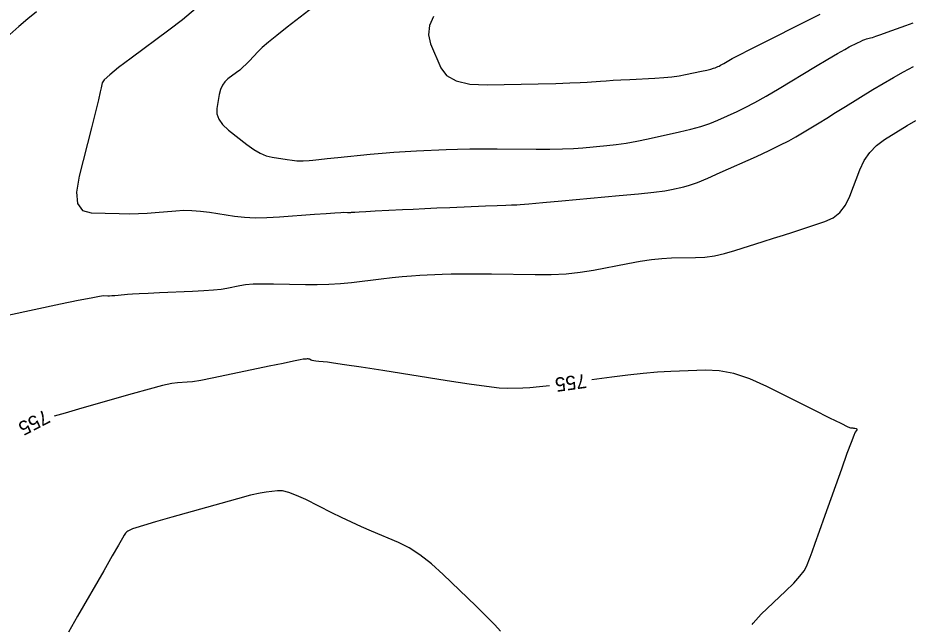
# Model space of a CAD drawing. Extents: x 2079879 to 2092887, y 778083 to 784051.
# Drawn here: x 2084668.2 to 2084844.9, y 781026.5 to 781146.9 of the extents above; entities that cross this region are included whole.
import ezdxf

# ---------------------------------------------------------------- set-up
doc = ezdxf.new("R2010")
doc.units = 0
doc.layers.add('DT_X_Contour_Major', color=7, linetype='Continuous')
doc.layers.add('DT_X_Contour_Minor', color=7, linetype='Continuous')

msp = doc.modelspace()

# ---------------------------------------------------------------- linework, layer by layer
at = {"layer": 'DT_X_Contour_Major'}
for points in [[(2084773.48, 781074.05), (2084771.5, 781073.82), (2084769.55, 781073.64), (2084768.14, 781073.57), (2084765.09, 781073.52), (2084763.49, 781073.59), (2084760.98, 781073.87), (2084757.55, 781074.34), (2084753.21, 781075), (2084740.41, 781077.03), (2084736.12, 781077.71), (2084732.88, 781078.21), (2084730.68, 781078.53), (2084729.51, 781078.69), (2084727.78, 781078.86), (2084727.2, 781078.92), (2084726.76, 781078.99), (2084726.44, 781079.05), (2084726.26, 781079.11), (2084725.94, 781079.27), (2084725.81, 781079.31), (2084725.66, 781079.34), (2084725.47, 781079.35), (2084725.26, 781079.33), (2084724.67, 781079.27), (2084724.08, 781079.16), (2084722.75, 781078.9), (2084720.7, 781078.47), (2084717.91, 781077.89), (2084709.51, 781076.12), (2084706.66, 781075.53), (2084704.41, 781075.1), (2084702.76, 781074.83), (2084701.72, 781074.72), (2084699.75, 781074.64), (2084698.63, 781074.48), (2084696.77, 781074.06), (2084694.15, 781073.37), (2084690.79, 781072.43), (2084680.82, 781069.57), (2084677.52, 781068.62), (2084675.32, 781068)], [(2084813.59, 781026.76), (2084813.79, 781027.06), (2084815.4, 781028.79), (2084820.22, 781033.4), (2084821.83, 781034.99), (2084823.06, 781036.33), (2084823.91, 781037.41), (2084824.36, 781038.24), (2084825.07, 781040.09), (2084825.45, 781041.13), (2084826.08, 781042.86), (2084826.95, 781045.28), (2084828.06, 781048.39), (2084831.34, 781057.62), (2084832.43, 781060.66), (2084833.24, 781062.87), (2084833.77, 781064.26), (2084834.01, 781064.81), (2084834.29, 781065.18), (2084834.37, 781065.31), (2084834.39, 781065.4), (2084834.35, 781065.47), (2084834.26, 781065.5), (2084833.95, 781065.56), (2084833.84, 781065.58), (2084833.72, 781065.59), (2084833.6, 781065.61), (2084833.47, 781065.62), (2084833.14, 781065.65), (2084832.6, 781065.87), (2084831.2, 781066.54), (2084828.96, 781067.64), (2084825.87, 781069.18), (2084816.51, 781073.86), (2084813.12, 781075.38), (2084809.96, 781076.43), (2084807.04, 781077.02), (2084804.36, 781077.15), (2084797.51, 781076.86), (2084794.85, 781076.7), (2084792.01, 781076.47), (2084788.99, 781076.14), (2084785.79, 781075.73), (2084781.8, 781075.18)]]:
    msp.add_lwpolyline(points, dxfattribs=at)
at = {"layer": 'DT_X_Contour_Minor'}
for points in [[(2084703.34, 781148.68), (2084700.76, 781146.5), (2084698.04, 781144.4), (2084690.57, 781138.89), (2084688.11, 781137.03), (2084686.34, 781135.6), (2084685.24, 781134.59), (2084684.83, 781134.01), (2084684.65, 781133.02), (2084684.48, 781132.24), (2084684.1, 781130.66), (2084683.51, 781128.28), (2084682.71, 781125.1), (2084680.31, 781115.53), (2084679.78, 781112.38), (2084679.99, 781110.12), (2084680.95, 781108.75), (2084682.65, 781108.26), (2084688.19, 781108.12), (2084690.2, 781108.1), (2084692.06, 781108.12), (2084693.79, 781108.19), (2084695.37, 781108.31), (2084699.41, 781108.68), (2084700.96, 781108.77), (2084702.6, 781108.75), (2084704.33, 781108.62), (2084706.13, 781108.39), (2084711.07, 781107.63), (2084713.01, 781107.4), (2084715.14, 781107.3), (2084717.46, 781107.31), (2084719.96, 781107.45), (2084726.89, 781107.98), (2084729.2, 781108.15), (2084730.93, 781108.28), (2084732.09, 781108.35), (2084732.66, 781108.37), (2084733.42, 781108.35), (2084733.69, 781108.35), (2084733.91, 781108.35), (2084734.09, 781108.35), (2084734.23, 781108.37), (2084734.55, 781108.4), (2084734.91, 781108.43), (2084735.75, 781108.48), (2084737.08, 781108.55), (2084738.89, 781108.64), (2084744.35, 781108.91), (2084746.48, 781109.01), (2084748.75, 781109.12), (2084751.16, 781109.23), (2084753.73, 781109.34), (2084760.76, 781109.64), (2084763.09, 781109.74), (2084764.81, 781109.81), (2084765.93, 781109.85), (2084766.43, 781109.86), (2084766.95, 781109.86), (2084767.65, 781109.91), (2084769.37, 781110.05), (2084772.11, 781110.3), (2084775.87, 781110.64), (2084787.24, 781111.68), (2084791.08, 781112.05), (2084794.09, 781112.37), (2084796.27, 781112.64), (2084797.61, 781112.86), (2084800.06, 781113.39), (2084801.2, 781113.72), (2084802.79, 781114.3), (2084804.81, 781115.13), (2084807.27, 781116.22), (2084814.43, 781119.45), (2084816.93, 781120.6), (2084819.07, 781121.63), (2084820.84, 781122.54), (2084822.25, 781123.34), (2084825.51, 781125.3), (2084826.84, 781126.1), (2084828.37, 781127.03), (2084830.1, 781128.1), (2084832.04, 781129.3), (2084837.49, 781132.67), (2084839.52, 781133.9), (2084841.55, 781135.08), (2084843.57, 781136.19), (2084845.57, 781137.25)], [(2084727.48, 781149.63), (2084721.48, 781144.99), (2084719.43, 781143.38), (2084717.79, 781142.04), (2084716.55, 781140.97), (2084715.71, 781140.16), (2084714.01, 781138.35), (2084713.38, 781137.7), (2084712.74, 781137.1), (2084712.09, 781136.54), (2084711.45, 781136.04), (2084709.73, 781134.77), (2084709.14, 781134.22), (2084708.66, 781133.53), (2084708.3, 781132.69), (2084708.05, 781131.71), (2084707.54, 781128.9), (2084707.54, 781127.85), (2084707.93, 781126.79), (2084708.71, 781125.72), (2084709.88, 781124.65), (2084713.53, 781121.79), (2084714.86, 781120.83), (2084716.14, 781120.09), (2084717.35, 781119.58), (2084718.49, 781119.29), (2084721.47, 781118.83), (2084722.51, 781118.68), (2084723.38, 781118.59), (2084724.08, 781118.55), (2084724.63, 781118.56), (2084725.85, 781118.65), (2084726.55, 781118.71), (2084727.74, 781118.82), (2084729.4, 781118.99), (2084731.55, 781119.21), (2084737.93, 781119.85), (2084740.29, 781120.08), (2084742.61, 781120.27), (2084744.88, 781120.42), (2084747.1, 781120.53), (2084752.96, 781120.78), (2084755.24, 781120.86), (2084757.69, 781120.91), (2084760.31, 781120.93), (2084763.11, 781120.93), (2084770.78, 781120.88), (2084773.52, 781120.88), (2084775.99, 781120.93), (2084778.17, 781121.03), (2084780.08, 781121.16), (2084784.79, 781121.6), (2084786.63, 781121.8), (2084788.61, 781122.09), (2084790.73, 781122.47), (2084793, 781122.94), (2084799.22, 781124.29), (2084801.45, 781124.81), (2084803.45, 781125.37), (2084805.22, 781125.97), (2084806.78, 781126.6), (2084810.62, 781128.34), (2084812.22, 781129.11), (2084814.14, 781130.12), (2084816.37, 781131.38), (2084818.92, 781132.89), (2084826.14, 781137.23), (2084828.58, 781138.69), (2084830.51, 781139.82), (2084831.91, 781140.62), (2084832.79, 781141.1), (2084834.45, 781141.93), (2084835.03, 781142.21), (2084835.52, 781142.43), (2084835.93, 781142.59), (2084836.25, 781142.69), (2084837, 781142.88), (2084837.42, 781143), (2084838.11, 781143.23), (2084839.08, 781143.57), (2084840.33, 781144.02), (2084844.03, 781145.34), (2084845.5, 781145.87)], [(2084671.86, 781148.06), (2084670.12, 781146.68), (2084668.34, 781145.17), (2084663.55, 781140.96)], [(2084750.46, 781147.16), (2084749.65, 781145.33), (2084749.47, 781143.52), (2084749.91, 781141.74), (2084751.93, 781137), (2084753.07, 781135.45), (2084754.97, 781134.37), (2084757.64, 781133.76), (2084761.07, 781133.61), (2084771.23, 781133.82), (2084774.7, 781133.9), (2084777.46, 781133.98), (2084779.52, 781134.06), (2084780.88, 781134.14), (2084783.58, 781134.34), (2084784.7, 781134.42), (2084786.03, 781134.5), (2084787.58, 781134.59), (2084789.34, 781134.68), (2084794.31, 781134.92), (2084796.09, 781135.04), (2084797.7, 781135.19), (2084799.13, 781135.38), (2084800.39, 781135.62), (2084803.53, 781136.3), (2084804.59, 781136.54), (2084805.4, 781136.73), (2084805.96, 781136.88), (2084806.28, 781136.99), (2084806.81, 781137.23), (2084807.03, 781137.33), (2084807.29, 781137.47), (2084807.6, 781137.65), (2084807.95, 781137.85), (2084808.94, 781138.45), (2084809.65, 781138.84), (2084811.05, 781139.56), (2084813.13, 781140.62), (2084815.89, 781142), (2084824.17, 781146.15), (2084827.06, 781147.56)], [(2084666.16, 781088.02), (2084676.62, 781090.23), (2084680.09, 781090.95), (2084682.66, 781091.47), (2084684.33, 781091.77), (2084685.1, 781091.87), (2084685.95, 781091.85), (2084686.32, 781091.85), (2084686.79, 781091.87), (2084687.35, 781091.91), (2084688.01, 781091.96), (2084689.9, 781092.14), (2084690.83, 781092.21), (2084692.18, 781092.29), (2084693.98, 781092.38), (2084696.21, 781092.48), (2084702.72, 781092.76), (2084704.98, 781092.87), (2084706.88, 781093.01), (2084708.4, 781093.18), (2084709.55, 781093.37), (2084712.13, 781093.91), (2084713.27, 781094.09), (2084714.76, 781094.19), (2084716.61, 781094.24), (2084718.8, 781094.22), (2084725.12, 781094.08), (2084727.46, 781094.06), (2084729.77, 781094.13), (2084732.03, 781094.28), (2084734.26, 781094.5), (2084740.13, 781095.22), (2084742.26, 781095.46), (2084744.25, 781095.66), (2084746.09, 781095.81), (2084747.8, 781095.91), (2084752.16, 781096.13), (2084754, 781096.19), (2084756.24, 781096.22), (2084758.89, 781096.22), (2084761.94, 781096.18), (2084770.6, 781096.04), (2084773.77, 781096.06), (2084776.75, 781096.21), (2084779.55, 781096.5), (2084782.18, 781096.94), (2084788.94, 781098.27), (2084791.39, 781098.72), (2084793.64, 781099.04), (2084795.71, 781099.24), (2084797.6, 781099.33), (2084802.37, 781099.4), (2084804.19, 781099.5), (2084806.1, 781099.77), (2084808.08, 781100.2), (2084810.15, 781100.79), (2084815.75, 781102.58), (2084817.8, 781103.24), (2084819.77, 781103.87), (2084821.63, 781104.47), (2084823.41, 781105.05), (2084828.01, 781106.54), (2084829.62, 781107.27), (2084830.97, 781108.35), (2084832.08, 781109.78), (2084832.95, 781111.56), (2084834.93, 781116.77), (2084835.78, 781118.6), (2084836.88, 781120.22), (2084838.21, 781121.6), (2084839.78, 781122.76), (2084844.27, 781125.54), (2084845.98, 781126.57)], [(2084725.16, 781051.5), (2084723.37, 781052.34), (2084721.84, 781052.91), (2084720.59, 781053.22), (2084719.61, 781053.26), (2084717.35, 781053), (2084716.15, 781052.79), (2084714.26, 781052.35), (2084711.66, 781051.67), (2084708.37, 781050.75), (2084698.65, 781048.01), (2084695.43, 781047.09), (2084693.06, 781046.4), (2084691.53, 781045.94), (2084690.86, 781045.71), (2084690.18, 781045.4), (2084689.94, 781045.28), (2084689.75, 781045.15), (2084689.59, 781045.01), (2084689.47, 781044.85), (2084689.22, 781044.43), (2084688.89, 781043.88), (2084688.11, 781042.51), (2084686.86, 781040.35), (2084685.16, 781037.39), (2084680, 781028.41), (2084678.16, 781025.28)], [(2084763.75, 781025.48), (2084762.62, 781026.7), (2084760.99, 781028.37), (2084758.83, 781030.47), (2084752.41, 781036.65), (2084750.05, 781038.79), (2084747.79, 781040.56), (2084745.63, 781041.96), (2084743.57, 781043), (2084738.21, 781045.27), (2084736.2, 781046.13), (2084734.22, 781047.03), (2084732.26, 781047.95), (2084730.32, 781048.91), (2084725.16, 781051.5)]]:
    msp.add_lwpolyline(points, dxfattribs=at)

# ---------------------------------------------------------------- texts
at = {"layer": 'DT_X_Contour_Major'}
for rotation, p in [(187.6793, (2084780.59, 781076.41)), (207.3614, (2084673.52, 781069.41))]:
    msp.add_text('755', height=2.8, rotation=rotation, dxfattribs=at).set_placement(p)

doc.saveas('drawing.dxf')
